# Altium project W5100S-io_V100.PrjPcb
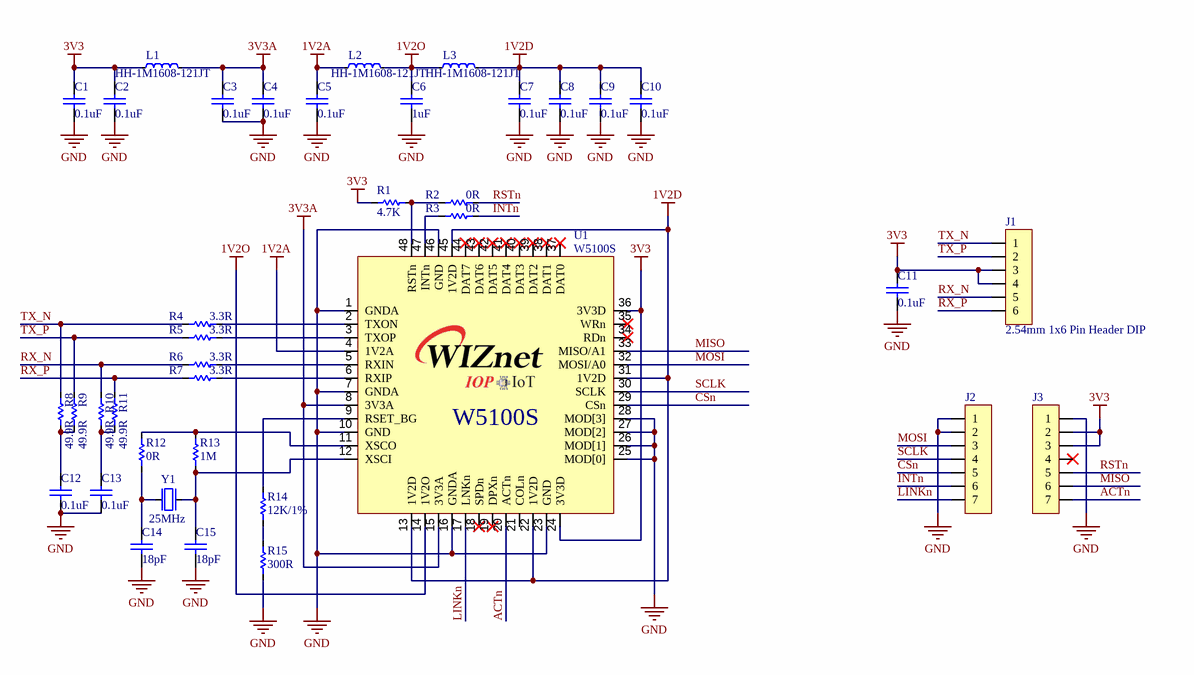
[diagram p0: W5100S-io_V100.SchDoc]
1 sheet, 38 parts. Net scope: global (net labels, ports and power ports of the same name join across sheets).
Board file: W5100S-io_V100.PcbDoc

## Sheet W5100S-io_V100.SchDoc: W5100S-io
size A4; DrawnBy: Scott; Revision: 100; SheetNumber: 1; SheetTotal: 1; Team: Edge

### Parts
C1  0.1uF  [CAP-0402]
C2  0.1uF  [CAP-0402]
C3  0.1uF  [CAP-0402]
C4  0.1uF  [CAP-0402]
C5  0.1uF  [CAP-0402]
C6  1uF  [CAP-0402]
C7  0.1uF  [CAP-0402]
C8  0.1uF  [CAP-0402]
C9  0.1uF  [CAP-0402]
C10  0.1uF  [CAP-0402]
C11  0.1uF  [CAP-0402]
C12  0.1uF  [CAP-0402]
C13  0.1uF  [CAP-0402]
C14  18pF  [CAP-0402]
C15  18pF  [CAP-0402]
J1  2.54mm 1x6 Pin Header DIP  [IDC-1X6(Wi510io)]
J2  2.54mm 1x7 Pin Header DIP  [IDC-1X7(Wi510io)]  (value not drawn)
J3  2.54mm 1x7 Pin Header DIP  [IDC-1X7(Wi510io)]  (value not drawn)
L1  HH-1M1608-121JT  [IND-0603]
L2  HH-1M1608-121JT  [IND-0603]
L3  HH-1M1608-121JT  [IND-0603]
R1  4.7K  [RES-0402]
R2  0R  [RES-0402]
R3  0R  [RES-0402]
R4  3.3R  [RES-0402]
R5  3.3R  [RES-0402]
R6  3.3R  [RES-0402]
R7  3.3R  [RES-0402]
R8  49.9R  [RES-0402]
R9  49.9R  [RES-0402]
R10  49.9R  [RES-0402]
R11  49.9R  [RES-0402]
R12  0R  [RES-0402]
R13  1M  [RES-0402]
R14  12K/1%  [RES-0402]
R15  300R  [RES-0402]
U1  W5100S  [LQFP48(0.5/9.0)]
Y1  25MHz  [OSC-82J0626]

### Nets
1V2A: C5.2 L2.1 U1.4(1V2A)
1V2D: C7.2 C8.2 C9.2 C10.2 L3.2 U1.13(1V2D) U1.22(1V2D) U1.31(1V2D) U1.45(1V2D)
1V2O: C6.2 L2.2 L3.1 U1.14(1V2O)
3V3: C1.2 C2.2 C11.2 J1.3 J1.4 J3.2 J3.3 L1.1 R1.1 U1.24(3V3D) U1.36(3V3D)
3V3A: C3.2 C4.2 L1.2 U1.8(3V3A) U1.15(3V3A)
GND: C1.1 C2.1 C3.1 C4.1 C5.1 C6.1 C7.1 C8.1 C9.1 C10.1 C11.1 C12.1 C13.1 C14.1 C15.1 J2.1 J2.2 J3.1 R15.2 U1.1(GNDA) U1.7(GNDA) U1.10(GND) U1.16(GNDA) U1.23(GND) U1.25(MOD[0]) U1.26(MOD[1]) U1.27(MOD[2]) U1.28(MOD[3]) U1.46(GND) Y1.2(GND) Y1.4(GND)
ACTn: J3.7 U1.20(ACTn)
CSn: J2.5 U1.29(CSn)
INTn: J2.6 R3.2
LINKn: J2.7 U1.17(LNKn)
MISO: J3.6 U1.33(MISO/A1)
MOSI: J2.3 U1.32(MOSI/A0)
RSTn: J3.5 R2.2
RX_N: J1.5 R6.1 R10.2
RX_P: J1.6 R7.1 R11.2
SCLK: J2.4 U1.30(SCLK)
TX_N: J1.1 R4.1 R8.2
TX_P: J1.2 R5.1 R9.2
NetC12_2: C12.2 R8.1 R9.1
NetC13_2: C13.2 R10.1 R11.1
NetC14_2: C14.2 R12.1 Y1.1(inp)
NetC15_2: C15.2 R13.1 U1.12(XSCI) Y1.3(out)
NetR1_2: R1.2 R2.1 U1.48(RSTn)
NetR3_1: R3.1 U1.47(INTn)
NetR4_2: R4.2 U1.2(TXON)
NetR5_2: R5.2 U1.3(TXOP)
NetR6_2: R6.2 U1.5(RXIN)
NetR7_2: R7.2 U1.6(RXIP)
NetR12_2: R12.2 R13.2 U1.11(XSCO)
NetR14_1: R14.1 U1.9(RSET_BG)
NetR14_2: R14.2 R15.1

Not connected (* = marked no-connect by the designer): J3 4*; U1 18(SPDn)* 19(DPXn)* 21(COLn) 34(RDn)* 35(WRn)* 37(DAT0)* 38(DAT1)* 39(DAT2)* 40(DAT3)* 41(DAT4)* 42(DAT5)* 43(DAT6)* 44(DAT7)*

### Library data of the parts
C1-C15 = CAP-0402: Ceramic CAP 0402(1005)
L1-L3 = IND-0603: Inductor 0603(1608)
R1-R15 = RES-0402
U1 = W5100S: WIZnet Hardwired TCP/IP Chip
Y1 = OSC-82J0626-25MHz: X-tal 25MHz,3.2x2.5 SMD, CL=18pF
